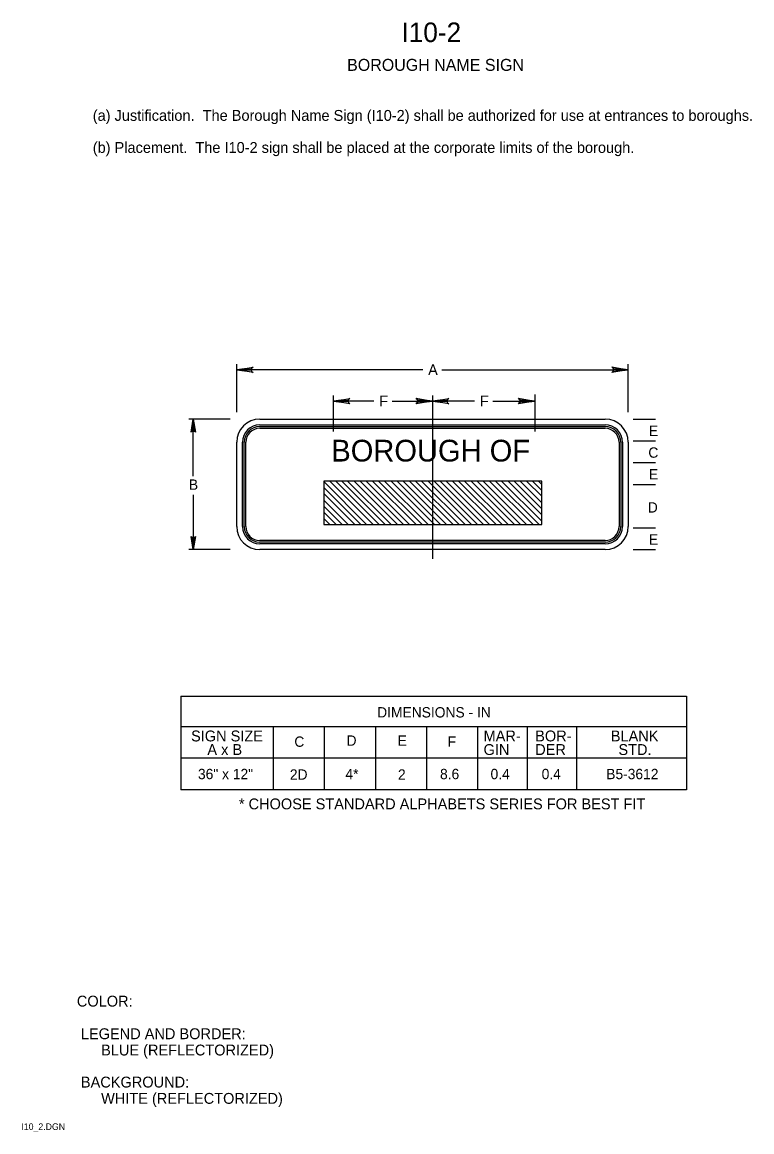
# Model space of a CAD drawing. Extents: x 0.013 to 0.18, y 0.004 to 0.259.
import ezdxf

# ---------------------------------------------------------------- set-up
doc = ezdxf.new("R2010")
doc.units = 0
for name, color, linetype in [('1', 7, 'Continuous'), ('2', 7, 'Continuous'), ('3', 7, 'Continuous')]:
    doc.layers.add(name, color=color, linetype=linetype)

# ---------------------------------------------------------------- blocks, each defined once
blk = doc.blocks.new('RARROW')
at = {"layer": '3'}
for p, q in [((-2.156, 0.285), (-2.2665, 0.384625)), ((-2.2665, 0.384625), (0, 0)), ((0, 0), (-2.2665, -0.379125)), ((-2.156, 0.285), (-2.075625, 0.12075)), ((0, 0), (-2.156, 0.285)), ((-2.14975, -0.2705), (0, 0)), ((-2.075625, 0.12075), (0, 0)), ((0, 0), (-2.074, -0.108)), ((-2.2665, -0.379125), (-2.14975, -0.2705)), ((-2.074, -0.108), (-2.14975, -0.2705))]:
    blk.add_line(p, q, dxfattribs=at)

msp = doc.modelspace()

# ---------------------------------------------------------------- linework, layer by layer
at = {"layer": '1'}
msp.add_line((0.107, 0.1733), (0.107, 0.13575), dxfattribs=at)
at = {"layer": '3'}
for p, q in [((0.062, 0.1695), (0.062, 0.1805)), ((0.10475, 0.17925), (0.062, 0.17925)), ((0.10912, 0.17925), (0.152, 0.17925)), ((0.152, 0.1695), (0.152, 0.1805)), ((0.08425, 0.16503), (0.08425, 0.17329)), ((0.09352, 0.17204), (0.08425, 0.17204)), ((0.09773, 0.17204), (0.107, 0.17204)), ((0.107, 0.17267), (0.107, 0.17079)), ((0.11665, 0.17204), (0.107, 0.17204)), ((0.12085, 0.17204), (0.1305, 0.17204)), ((0.1305, 0.17354), (0.1305, 0.16503)), ((0.06051, 0.16787), (0.051, 0.16787)), ((0.052, 0.15475), (0.052, 0.16787)), ((0.0673, 0.16787), (0.1467, 0.16787)), ((0.0673, 0.16657), (0.1467, 0.16657)), ((0.0673, 0.16617), (0.1467, 0.16617)), ((0.15313, 0.16787), (0.15825, 0.16787)), ((0.0673, 0.16577), (0.1467, 0.16577)), ((0.062, 0.14318), (0.062, 0.16257)), ((0.0633, 0.14318), (0.0633, 0.16257)), ((0.0637, 0.14318), (0.0637, 0.16257)), ((0.0641, 0.14318), (0.0641, 0.16257)), ((0.1499, 0.16257), (0.1499, 0.14318)), ((0.1503, 0.16257), (0.1503, 0.14318)), ((0.1507, 0.16257), (0.1507, 0.14318)), ((0.152, 0.16257), (0.152, 0.14318)), ((0.15313, 0.16287), (0.15825, 0.16287)), ((0.15313, 0.15788), (0.15825, 0.15788)), ((0.082, 0.1535), (0.09187, 0.14363)), ((0.08338, 0.15363), (0.09337, 0.14363)), ((0.08475, 0.15363), (0.09475, 0.14363)), ((0.08613, 0.15363), (0.09613, 0.14363)), ((0.0875, 0.15363), (0.0975, 0.14363)), ((0.089, 0.15363), (0.099, 0.14363)), ((0.09037, 0.15363), (0.10038, 0.14363)), ((0.09175, 0.15363), (0.10175, 0.14363)), ((0.09325, 0.15363), (0.10325, 0.14363)), ((0.09463, 0.15363), (0.10462, 0.14363)), ((0.096, 0.15363), (0.106, 0.14363)), ((0.0975, 0.15363), (0.1075, 0.14363)), ((0.09888, 0.15363), (0.10887, 0.14363)), ((0.10025, 0.15363), (0.11025, 0.14363)), ((0.10175, 0.15363), (0.11175, 0.14363)), ((0.10313, 0.15363), (0.11313, 0.14363)), ((0.1045, 0.15363), (0.1145, 0.14363)), ((0.106, 0.15363), (0.116, 0.14363)), ((0.10737, 0.15363), (0.11738, 0.14363)), ((0.10875, 0.15363), (0.11875, 0.14363)), ((0.11013, 0.15363), (0.12012, 0.14363)), ((0.11163, 0.15363), (0.12162, 0.14363)), ((0.113, 0.15363), (0.123, 0.14363)), ((0.11438, 0.15363), (0.12437, 0.14363)), ((0.11588, 0.15363), (0.12588, 0.14363)), ((0.11725, 0.15363), (0.12725, 0.14363)), ((0.11863, 0.15363), (0.12862, 0.14363)), ((0.12012, 0.15363), (0.13012, 0.14363)), ((0.1215, 0.15363), (0.1315, 0.14363)), ((0.12287, 0.15363), (0.13212, 0.14438)), ((0.12437, 0.15363), (0.13212, 0.14588)), ((0.12575, 0.15363), (0.13212, 0.14725)), ((0.12713, 0.15363), (0.13212, 0.14863)), ((0.12862, 0.15363), (0.13212, 0.15013)), ((0.13, 0.15363), (0.13212, 0.1515)), ((0.13137, 0.15363), (0.13212, 0.15288)), ((0.082, 0.15213), (0.0905, 0.14363)), ((0.082, 0.15075), (0.08912, 0.14363)), ((0.15313, 0.15288), (0.15825, 0.15288)), ((0.052, 0.1505), (0.052, 0.13787)), ((0.082, 0.14925), (0.08763, 0.14363)), ((0.082, 0.14788), (0.08625, 0.14363)), ((0.082, 0.1465), (0.08488, 0.14363)), ((0.082, 0.145), (0.08338, 0.14363)), ((0.082, 0.14363), (0.082, 0.14363)), ((0.15313, 0.14288), (0.15825, 0.14288)), ((0.06051, 0.13787), (0.051, 0.13787)), ((0.1467, 0.13998), (0.0673, 0.13998)), ((0.1467, 0.13958), (0.0673, 0.13958)), ((0.1467, 0.13918), (0.0673, 0.13918)), ((0.1467, 0.13787), (0.0673, 0.13787)), ((0.15313, 0.13787), (0.15825, 0.13787)), ((0.04913, 0.10412), (0.16537, 0.10412)), ((0.04913, 0.10412), (0.04913, 0.08263)), ((0.16537, 0.10412), (0.16537, 0.08263)), ((0.16537, 0.09713), (0.04913, 0.09713)), ((0.07039, 0.09724), (0.07039, 0.08262)), ((0.08213, 0.09713), (0.08213, 0.08263)), ((0.09388, 0.09713), (0.09388, 0.08263)), ((0.10562, 0.09713), (0.10562, 0.08263)), ((0.11739, 0.09724), (0.11739, 0.08262)), ((0.12877, 0.09724), (0.12877, 0.08262)), ((0.14014, 0.09724), (0.14014, 0.08262)), ((0.16537, 0.08987), (0.04913, 0.08987)), ((0.16537, 0.08263), (0.04913, 0.08263))]:
    msp.add_line(p, q, dxfattribs=at)
msp.add_lwpolyline([(0.13212, 0.15363), (0.082, 0.15363), (0.082, 0.14363), (0.13212, 0.14363)], close=True, dxfattribs=at)
for centre, radius, start, end in [((0.0673, 0.16257), 0.0053, 90, 180), ((0.0673, 0.16257), 0.004, 90, 180), ((0.0673, 0.16257), 0.0036, 90, 180), ((0.1467, 0.16257), 0.0053, 0, 90), ((0.1467, 0.16257), 0.004, 0, 90), ((0.1467, 0.16257), 0.0036, 0, 90), ((0.0673, 0.16257), 0.0032, 90, 180), ((0.1467, 0.16257), 0.0032, 0, 90), ((0.0673, 0.14318), 0.0053, 180, 270), ((0.0673, 0.14318), 0.004, 180, 270), ((0.0673, 0.14318), 0.0036, 180, 270), ((0.0673, 0.14318), 0.0032, 180, 270), ((0.1467, 0.14318), 0.0053, 270, 0), ((0.1467, 0.14318), 0.004, 270, 0), ((0.1467, 0.14318), 0.0036, 270, 0), ((0.1467, 0.14318), 0.0032, 270, 0)]:
    msp.add_arc(centre, radius, start, end, dxfattribs=at)

# ---------------------------------------------------------------- block references
for p, xscale, yscale, rotation in [((0.062, 0.17925), 0.0016545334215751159, 0.0016366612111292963, 180), ((0.08425, 0.17204), 0.0016545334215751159, 0.0016366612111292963, 180), ((0.107, 0.17204), 0.0016545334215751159, 0.0016366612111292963, 180), ((0.052, 0.16787), 0.0013236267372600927, 0.001309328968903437, 90), ((0.052, 0.13787), 0.0013236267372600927, 0.001309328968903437, -90)]:
    msp.add_blockref('RARROW', p, dxfattribs=dict(at, xscale=xscale, yscale=yscale, rotation=rotation))
at = {"layer": '3', "xscale": 0.0016545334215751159, "yscale": 0.0016366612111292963}
for p in [(0.152, 0.17925), (0.107, 0.17204), (0.1305, 0.17204)]:
    msp.add_blockref('RARROW', p, dxfattribs=at)

# ---------------------------------------------------------------- texts
at = {"layer": '1'}
for s, height, p in [('I10-2', 0.0045, (0.09988, 0.25462)), ('BOROUGH NAME SIGN', 0.0027503, (0.08738, 0.248)), ('COLOR:', 0.0025, (0.02525, 0.03275)), (' LEGEND AND BORDER:', 0.0024998, (0.02525, 0.02525)), ('      BLUE (REFLECTORIZED)', 0.0024998, (0.02525, 0.0215)), (' BACKGROUND:', 0.0024998, (0.02525, 0.01413)), ('      WHITE (REFLECTORIZED)', 0.0024998, (0.02525, 0.01038)), ('I10_2.DGN', 0.0015, (0.0125, 0.00438))]:
    msp.add_text(s, height=height, dxfattribs=at).set_placement(p)
at = {"layer": '2'}
for s, height, p in [('   (a) Justification.  The Borough Name Sign (I10-2) shall be authorized for use at entrances to boroughs.', 0.00249975, (0.02612, 0.2365)), ('   (b) Placement.  The I10-2 sign shall be placed at the corporate limits of the borough.', 0.0024998, (0.02612, 0.22912))]:
    msp.add_text(s, height=height, dxfattribs=at).set_placement(p)
at = {"layer": '3'}
for s, height, p in [('A', 0.0025, (0.106, 0.178)), ('F', 0.0025, (0.09477, 0.17079)), ('F', 0.0025, (0.1179, 0.17079)), ('E', 0.00238, (0.15675, 0.164)), ('BOROUGH OF', 0.005, (0.08375, 0.15813)), ('C', 0.00238, (0.15663, 0.159)), ('E', 0.00238, (0.15675, 0.154)), ('B', 0.00238, (0.051, 0.15163)), ('D', 0.00238, (0.1565, 0.14638)), ('E', 0.00238, (0.15675, 0.139)), ('DIMENSIONS - IN', 0.0023752, (0.09429, 0.09925)), ('SIGN SIZE', 0.0025, (0.0515, 0.09375)), ('C', 0.00238, (0.07525, 0.0925)), ('D', 0.00238, (0.08725, 0.09275)), ('E', 0.00238, (0.099, 0.09275)), ('F', 0.00238, (0.1105, 0.0925)), ('MAR-', 0.0025, (0.11875, 0.09375)), ('BOR-', 0.0025, (0.13062, 0.09375)), ('BLANK', 0.0025, (0.148, 0.09375)), ('A x B', 0.0025, (0.05525, 0.09062)), ('GIN', 0.0025, (0.11875, 0.09062)), ('DER', 0.0025, (0.13062, 0.09062)), ('STD.', 0.0025, (0.14975, 0.09062)), ('36" x 12"', 0.002375, (0.05309, 0.08506)), ('2D', 0.002375, (0.07422, 0.08494)), ('4*', 0.002375, (0.08699, 0.08506)), ('2', 0.00238, (0.09907, 0.08494)), ('8.6', 0.002375, (0.10874, 0.08506)), ('0.4', 0.002375, (0.12036, 0.08506)), ('0.4', 0.002375, (0.13211, 0.08506)), ('B5-3612', 0.002375, (0.14695, 0.08506)), ('* CHOOSE STANDARD ALPHABETS SERIES FOR BEST FIT', 0.0024998, (0.0625, 0.07812))]:
    msp.add_text(s, height=height, dxfattribs=at).set_placement(p)

doc.saveas('drawing.dxf')
